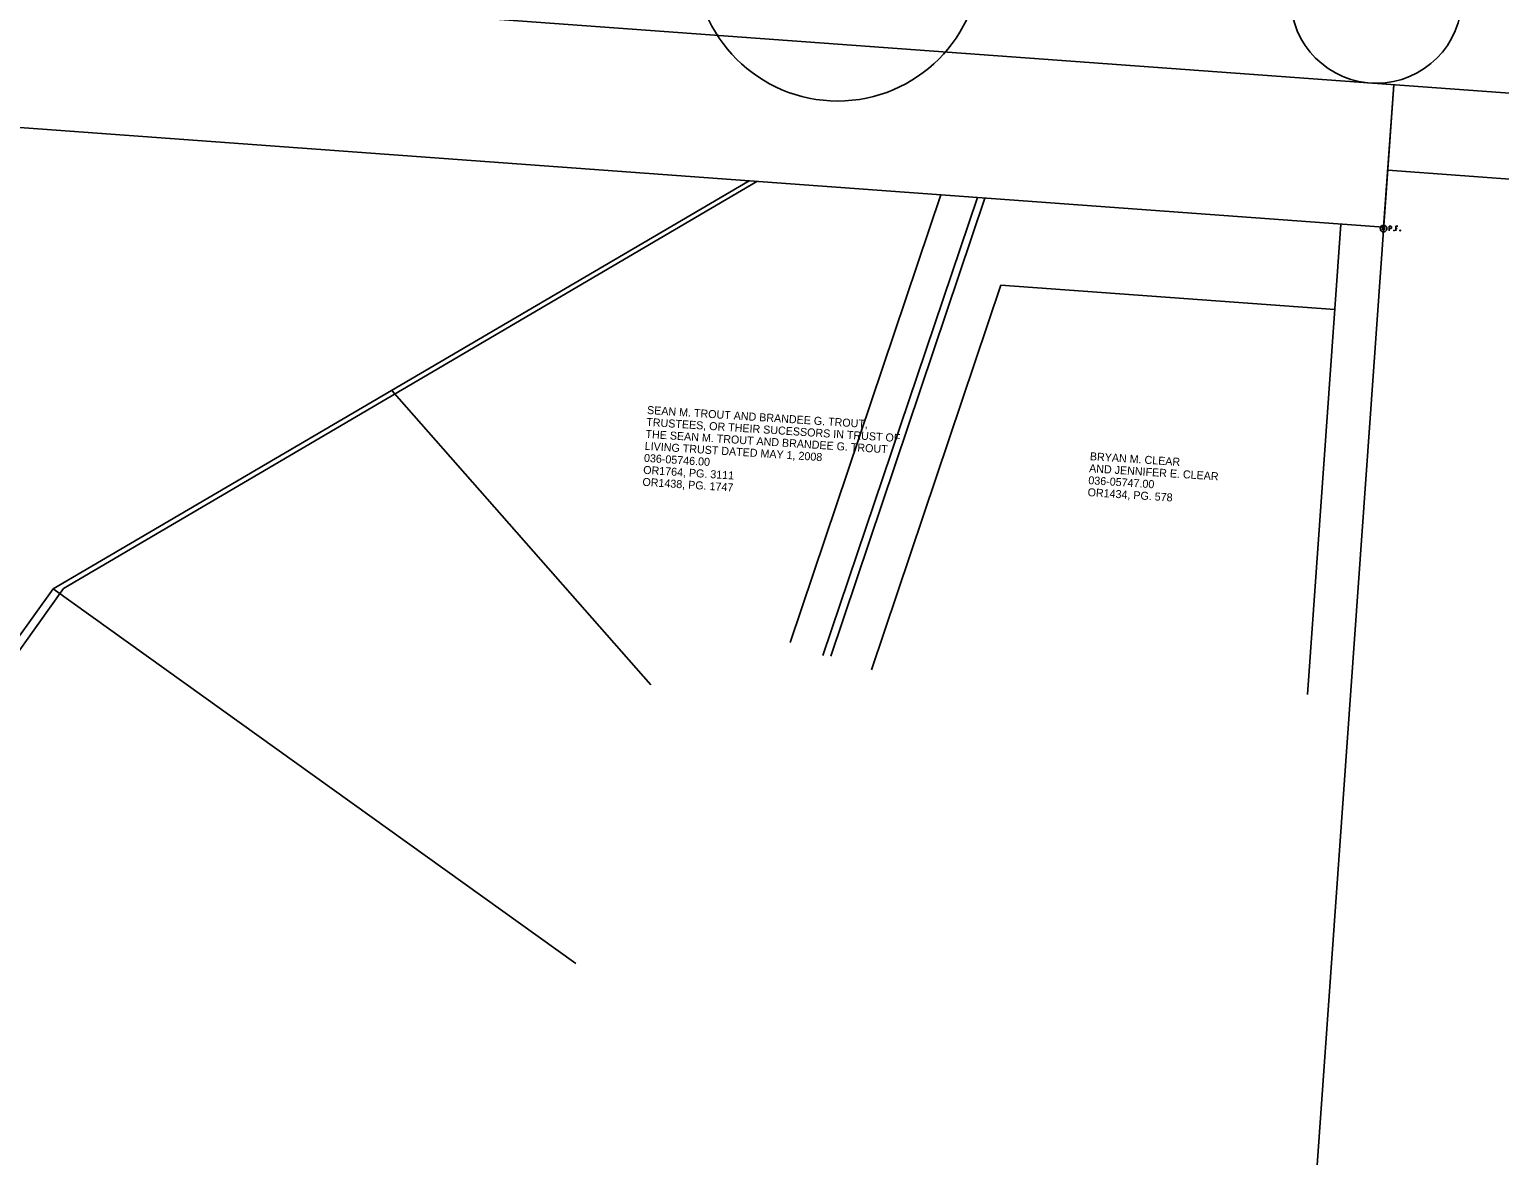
# Model space of a CAD drawing. Extents: x 1898254 to 1901377, y 701554 to 704886.
# Drawn here: x 1900133 to 1900647, y 702797 to 703191 of the extents above; entities that cross this region are included whole.
import ezdxf

# ---------------------------------------------------------------- set-up
doc = ezdxf.new("R2010")
doc.units = 0
for name, color, linetype in [('DV_X_Property_Line', 7, 'Continuous'), ('DV_X_Text', 7, 'Continuous'), ('RW_X_CL', 7, 'Continuous'), ('RW_X_Esmt_SH', 7, 'Continuous'), ('RW_X_Esmt_SW', 7, 'Continuous'), ('RW_X_Esmt_U', 7, 'Continuous'), ('RW_X_Fee_RW', 7, 'Continuous'), ('SC_Scratch1', 7, 'Continuous'), ('SC_Scratch2', 7, 'Continuous'), ('SC_Scratch3', 7, 'Continuous'), ('SC_Scratch6', 7, 'Continuous'), ('SC_Scratch9', 7, 'Continuous'), ('SV_X_Mon_Cells_Found', 7, 'Continuous')]:
    doc.layers.add(name, color=color, linetype=linetype)

msp = doc.modelspace()

# ---------------------------------------------------------------- linework, layer by layer
at = {"layer": 'DV_X_Property_Line'}
msp.add_line((1900573.07, 702649.15), (1900610.16, 703171.77), dxfattribs=at)
at = {"layer": 'RW_X_CL'}
msp.add_line((1899815.76, 703229.84), (1901162.17, 703131.42), dxfattribs=at)
at = {"layer": 'RW_X_Esmt_SH'}
msp.add_line((1900608.03, 703141.85), (1901159.98, 703101.5), dxfattribs=at)
at = {"layer": 'RW_X_Esmt_SW'}
for p, q in [((1900399.03, 702976.61), (1900451.69, 703133.22)), ((1900427.46, 702967.05), (1900472.71, 703101.6)), ((1900472.71, 703101.6), (1900589.53, 703093.06))]:
    msp.add_line(p, q, dxfattribs=at)
at = {"layer": 'RW_X_Esmt_U'}
msp.add_line((1900579.98, 702958.41), (1900591.66, 703122.99), dxfattribs=at)
at = {"layer": 'RW_X_Fee_RW'}
for p, q in [((1899868.13, 703175.88), (1900606.62, 703121.9)), ((1900606.62, 703121.9), (1900610.16, 703171.77))]:
    msp.add_line(p, q, dxfattribs=at)
at = {"layer": 'SC_Scratch1'}
msp.add_circle((1900604.03, 703202.3), 30, dxfattribs=at)
at = {"layer": 'SC_Scratch2'}
msp.add_circle((1899815.76, 703229.84), 1561.35, dxfattribs=at)
at = {"layer": 'SC_Scratch3'}
msp.add_circle((1900415.61, 703216.07), 50, dxfattribs=at)
at = {"layer": 'SC_Scratch6'}
for p, q in [((1900144.84, 702995.46), (1900387.35, 703137.92)), ((1900413.24, 702971.83), (1900467.13, 703132.09)), ((1900003.06, 702797.06), (1900144.84, 702995.46))]:
    msp.add_line(p, q, dxfattribs=at)
at = {"layer": 'SC_Scratch9'}
for p, q in [((1900141.16, 702995.38), (1900384.72, 703138.12)), ((1900410.45, 702972.08), (1900464.51, 703132.28)), ((1900350.32, 702961.74), (1900259.61, 703064.8)), ((1899999.17, 702797.13), (1900141.16, 702995.38)), ((1900141.16, 702995.38), (1900324.05, 702864.31))]:
    msp.add_line(p, q, dxfattribs=at)
at = {"layer": 'SV_X_Mon_Cells_Found'}
for points in [[(1900608.58, 703120.64), (1900608.58, 703122.24), (1900609.11, 703122.24), (1900609.17, 703122.23), (1900609.24, 703122.2), (1900609.28, 703122.18), (1900609.31, 703122.15), (1900609.35, 703122.09), (1900609.39, 703122.03), (1900609.41, 703121.93), (1900609.41, 703121.78), (1900609.4, 703121.73), (1900609.38, 703121.65), (1900609.33, 703121.56), (1900609.29, 703121.52), (1900609.26, 703121.5), (1900609.2, 703121.47), (1900609.11, 703121.46), (1900608.58, 703121.46)], [(1900611.59, 703122.24), (1900610.83, 703122.24), (1900610.83, 703120.64)], [(1900610.23, 703120.86), (1900610.28, 703120.86), (1900610.31, 703120.83), (1900610.35, 703120.78), (1900610.35, 703120.72), (1900610.31, 703120.67), (1900610.28, 703120.64), (1900610.23, 703120.64), (1900610.19, 703120.67), (1900610.16, 703120.72), (1900610.16, 703120.78), (1900610.19, 703120.83), (1900610.23, 703120.86)], [(1900610.83, 703121.46), (1900611.37, 703121.46)], [(1900612.37, 703120.86), (1900612.43, 703120.86), (1900612.46, 703120.83), (1900612.5, 703120.78), (1900612.5, 703120.72), (1900612.46, 703120.67), (1900612.43, 703120.64), (1900612.37, 703120.64), (1900612.34, 703120.67), (1900612.31, 703120.72), (1900612.31, 703120.78), (1900612.34, 703120.83), (1900612.37, 703120.86)]]:
    msp.add_lwpolyline(points, dxfattribs=at)
for radius in [1.2, 0.495]:
    msp.add_circle((1900606.59, 703121.44), radius, dxfattribs=at)

# ---------------------------------------------------------------- texts
at = {"layer": 'DV_X_Text'}
for s, p in [('SEAN M. TROUT AND BRANDEE G. TROUT, ', (1900348.87, 703056.59)), ('THE SEAN M. TROUT AND BRANDEE G. TROUT ', (1900348.33, 703048.21)), ('TRUSTEES, OR THEIR SUCESSORS IN TRUST OF ', (1900348.6, 703052.4)), ('LIVING TRUST DATED MAY 1, 2008', (1900348.06, 703044.02)), ('036-05746.00', (1900347.8, 703039.83)), ('BRYAN M. CLEAR', (1900503.79, 703040.4)), ('OR1764, PG. 3111 ', (1900347.53, 703035.64)), ('036-05747.00', (1900503.25, 703032.02)), ('AND JENNIFER E. CLEAR', (1900503.52, 703036.21)), ('OR1438, PG. 1747', (1900347.26, 703031.45)), ('OR1434, PG. 578', (1900502.99, 703027.82))]:
    msp.add_text(s, height=2.8, rotation=356.3351, dxfattribs=at).set_placement(p)

doc.saveas('drawing.dxf')
